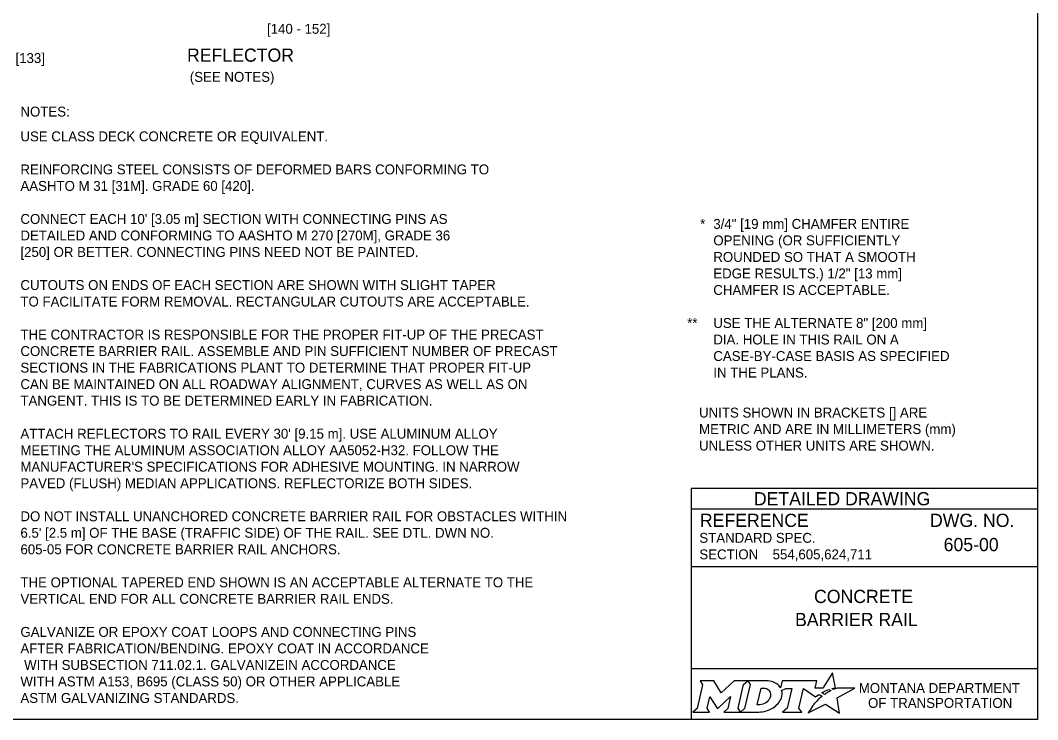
# Model space of a CAD drawing. Extents: x 49991.4 to 50021, y 49987.6 to 50011.4.
# Drawn here: x 50010.59 to 50016.75, y 49987.8 to 49992.03 of the extents above; entities that cross this region are included whole.
import ezdxf

# ---------------------------------------------------------------- set-up
doc = ezdxf.new("R2010")
doc.units = 0
for name, color, linetype in [('Default', 7, 'Continuous'), ('Level 1', 7, 'Continuous'), ('Level 2', 7, 'Continuous'), ('Level 3', 7, 'Continuous'), ('Level 5', 7, 'Continuous')]:
    doc.layers.add(name, color=color, linetype=linetype)

msp = doc.modelspace()

# ---------------------------------------------------------------- linework, layer by layer
at = {"layer": 'Default'}
for points in [[(50014.7056, 49988.0338), (50014.7197, 49988.0104), (50014.6862, 49987.8671), (50014.6605, 49987.8446), (50014.7621, 49987.8446), (50014.7486, 49987.8674), (50014.7648, 49987.9375), (50014.8085, 49987.8685), (50014.8138, 49987.8685), (50014.8889, 49987.938), (50014.8725, 49987.8669), (50014.8478, 49987.8449), (50014.9494, 49987.8449), (50014.9356, 49987.8682), (50014.9688, 49988.0106)], [(50014.9688, 49988.0106), (50014.9941, 49988.0338), (50014.9117, 49988.0338), (50014.8321, 49987.9608), (50014.7876, 49988.0335), (50014.7056, 49988.0338)], [(50015.1077, 49988.0338), (50014.9941, 49988.0338), (50015.0088, 49988.0109), (50014.9749, 49987.8671), (50014.9494, 49987.8449), (50015.06, 49987.8449)], [(50015.5126, 49987.9811), (50015.5023, 49987.9867), (50015.5139, 49987.9895), (50015.5255, 49987.9915), (50015.5081, 49988.0816), (50015.4486, 49987.9903), (50015.4013, 49987.9896), (50015.4116, 49988.0337), (50015.2024, 49988.0338), (50015.1923, 49987.9913), (50015.1865, 49987.9996)], [(50015.1317, 49987.9471), (50015.1305, 49987.939), (50015.1273, 49987.9297), (50015.1231, 49987.9215), (50015.1175, 49987.914), (50015.111, 49987.9071), (50015.1031, 49987.9008), (50015.0948, 49987.8961), (50015.0857, 49987.8922), (50015.0766, 49987.8899), (50015.0674, 49987.889), (50015.0515, 49987.889), (50015.0751, 49987.989), (50015.0911, 49987.989), (50015.0987, 49987.9884), (50015.1063, 49987.9865), (50015.1129, 49987.9835), (50015.119, 49987.9793), (50015.1238, 49987.9743), (50015.1275, 49987.9683), (50015.1302, 49987.9621), (50015.1318, 49987.9547), (50015.1318, 49987.9517), (50015.1317, 49987.9471)], [(50015.1991, 49987.9747), (50015.2237, 49987.9878), (50015.2606, 49987.9878), (50015.232, 49987.8673), (50015.2045, 49987.8446), (50015.3207, 49987.8446), (50015.3037, 49987.8675), (50015.3319, 49987.9877), (50015.4032, 49987.936), (50015.4243, 49987.9511), (50015.444, 49987.9402)], [(50015.3882, 49987.8843), (50015.3729, 49987.8599), (50015.3682, 49987.8524), (50015.3624, 49987.8438), (50015.3601, 49987.8395), (50015.4654, 49987.8926), (50015.5493, 49987.8375), (50015.5362, 49987.9302), (50015.6431, 49987.9886), (50015.5938, 49987.9894), (50015.5637, 49987.9898), (50015.5429, 49987.9901), (50015.5361, 49987.9886), (50015.5312, 49987.9874), (50015.5228, 49987.9851), (50015.5126, 49987.9811)], [(50015.4622, 49987.9535), (50015.4598, 49987.9518), (50015.4415, 49987.9614), (50015.4518, 49987.9671), (50015.4559, 49987.9693), (50015.4645, 49987.9733), (50015.4702, 49987.9759), (50015.4781, 49987.9789), (50015.4854, 49987.9816), (50015.4972, 49987.9742), (50015.4932, 49987.9721), (50015.4886, 49987.9696), (50015.4844, 49987.9674), (50015.4794, 49987.9645), (50015.4775, 49987.9634), (50015.4748, 49987.9618), (50015.4723, 49987.9604), (50015.47, 49987.9588), (50015.4674, 49987.957), (50015.4647, 49987.9552), (50015.4622, 49987.9535)], [(50015.1057, 49987.8522), (50015.1141, 49987.8548), (50015.1271, 49987.8602), (50015.1475, 49987.8712)], [(50015.4021, 49987.9004), (50015.4021, 49987.9004)]]:
    msp.add_lwpolyline(points, dxfattribs=at)
for centre, radius, start, end in [((50015.1308, 49987.9554), 0.0709, 339.53292, 15.85821), ((50015.0868, 49987.9727), 0.1183, 300.91025, 339.13831)]:
    msp.add_arc(centre, radius, start, end, dxfattribs=at)
for centre, major_axis, ratio, start_param, end_param in [((50015.1056, 49987.9864), (0.0834, -0.0037), 0.568097, 0.61298, 1.570796), ((50015.1612, 49987.9937), (0.0361, -0.0295), 0.469099, 1.225588, 1.570796), ((50015.4119, 49987.9106), (-0.0098, -0.0102), 0.016458, 3.141593, 6.279097), ((50015.4329, 49987.9305), (-0.0112, -0.0097), 0.021651, 3.157348, 6.283185), ((50015.0603, 49987.9932), (0, 0.1484), 0.987302, 3.139398, 3.456847), ((50015.3952, 49987.8923), (-0.00694, -0.00806), 0.008222, 0, 3.137361)]:
    msp.add_ellipse(centre, major_axis=major_axis, ratio=ratio, start_param=start_param, end_param=end_param, dxfattribs=at)
at = {"layer": 'Level 1'}
msp.add_lwpolyline([(49999.3835, 49998.9992), (50016.7501, 49998.9992), (50016.7501, 49987.7988), (49999.3835, 49987.7988)], close=True, dxfattribs=at)
at = {"layer": 'Level 5'}
for p, q in [((50016.7501, 49989.1988), (50014.6501, 49989.1988)), ((50014.6501, 49989.1988), (50014.6501, 49987.7988)), ((50016.7501, 49989.0738), (50014.6501, 49989.0738)), ((50016.3862, 49988.8587), (50016.3862, 49988.8587)), ((50015.1444, 49988.7993), (50015.1444, 49988.7993)), ((50016.7501, 49988.7238), (50014.6501, 49988.7238)), ((50015.7001, 49988.4747), (50015.7001, 49988.4747)), ((50016.7501, 49988.1057), (50014.6501, 49988.1057))]:
    msp.add_line(p, q, dxfattribs=at)

# ---------------------------------------------------------------- texts
at = {"layer": 'Default'}
for s, p in [('MONTANA DEPARTMENT', (50015.6663, 49987.96)), ('OF TRANSPORTATION', (50015.7225, 49987.87))]:
    msp.add_text(s, height=0.06, dxfattribs=at).set_placement(p)
at = {"layer": 'Level 2'}
for s, height, p in [('[140 - 152]', 0.06, (50012.0809, 49991.9511)), ('REFLECTOR', 0.08, (50011.5965, 49991.7817)), ('5 1/4" [133]', 0.06, (50010.3279, 49991.774)), ('(SEE NOTES)', 0.06, (50011.6132, 49991.6601)), ('NOTES:', 0.06, (50010.587, 49991.4499)), ('*', 0.06, (50014.7054, 49990.77)), ('3/4" [19 mm] CHAMFER ENTIRE ', 0.06, (50014.7851, 49990.77)), ('OPENING (OR SUFFICIENTLY ', 0.06, (50014.7851, 49990.67)), ('ROUNDED SO THAT A SMOOTH ', 0.06, (50014.7851, 49990.57)), ('EDGE RESULTS.) 1/2" [13 mm] ', 0.06, (50014.7851, 49990.47)), ('CHAMFER IS ACCEPTABLE.', 0.06, (50014.7851, 49990.37)), ('**', 0.06, (50014.6266, 49990.17)), ('USE THE ALTERNATE 8" [200 mm] ', 0.06, (50014.7851, 49990.17)), ('DIA. HOLE IN THIS RAIL ON A ', 0.06, (50014.7851, 49990.07)), ('CASE-BY-CASE BASIS AS SPECIFIED', 0.06, (50014.7851, 49989.97)), ('IN THE PLANS.', 0.06, (50014.7851, 49989.87)), ('UNITS SHOWN IN BRACKETS [] ARE ', 0.06, (50014.6987, 49989.6278)), ('METRIC AND ARE IN MILLIMETERS (mm) ', 0.06, (50014.6987, 49989.5278)), ('UNLESS OTHER UNITS ARE SHOWN.', 0.06, (50014.6987, 49989.4278)), ('605-00', 0.08, (50016.1806, 49988.8187)), ('554,605,624,711', 0.059999, (50015.1444, 49988.7693)), ('CONCRETE', 0.08, (50015.3953, 49988.5047)), ('BARRIER RAIL', 0.079998, (50015.2803, 49988.3647))]:
    msp.add_text(s, height=height, dxfattribs=at).set_placement(p)
at = {"layer": 'Level 3'}
for s, p in [('USE CLASS DECK CONCRETE OR EQUIVALENT.', (50010.587, 49991.2999)), ('REINFORCING STEEL CONSISTS OF DEFORMED BARS CONFORMING TO ', (50010.587, 49991.0999)), ('AASHTO M 31 [31M]. GRADE 60 [420].', (50010.587, 49990.9999)), ("CONNECT EACH 10' [3.05 m] SECTION WITH CONNECTING PINS AS", (50010.587, 49990.7999)), ('DETAILED AND CONFORMING TO AASHTO M 270 [270M], GRADE 36 ', (50010.587, 49990.6999)), ('[250] OR BETTER. CONNECTING PINS NEED NOT BE PAINTED.', (50010.587, 49990.5999)), ('CUTOUTS ON ENDS OF EACH SECTION ARE SHOWN WITH SLIGHT TAPER', (50010.587, 49990.3999)), ('TO FACILITATE FORM REMOVAL. RECTANGULAR CUTOUTS ARE ACCEPTABLE.', (50010.587, 49990.2999)), ('THE CONTRACTOR IS RESPONSIBLE FOR THE PROPER FIT-UP OF THE PRECAST', (50010.587, 49990.0999)), ('CONCRETE BARRIER RAIL. ASSEMBLE AND PIN SUFFICIENT NUMBER OF PRECAST ', (50010.587, 49989.9999)), ('SECTIONS IN THE FABRICATIONS PLANT TO DETERMINE THAT PROPER FIT-UP', (50010.587, 49989.8999)), ('CAN BE MAINTAINED ON ALL ROADWAY ALIGNMENT, CURVES AS WELL AS ON ', (50010.587, 49989.7999)), ('TANGENT. THIS IS TO BE DETERMINED EARLY IN FABRICATION.', (50010.587, 49989.6999)), ("ATTACH REFLECTORS TO RAIL EVERY 30' [9.15 m]. USE ALUMINUM ALLOY", (50010.587, 49989.4999)), ('MEETING THE ALUMINUM ASSOCIATION ALLOY AA5052-H32. FOLLOW THE ', (50010.587, 49989.3999)), ("MANUFACTURER'S SPECIFICATIONS FOR ADHESIVE MOUNTING. IN NARROW", (50010.587, 49989.2999)), ('PAVED (FLUSH) MEDIAN APPLICATIONS. REFLECTORIZE BOTH SIDES.', (50010.587, 49989.1999)), ('DO NOT INSTALL UNANCHORED CONCRETE BARRIER RAIL FOR OBSTACLES WITHIN', (50010.587, 49988.9999)), ("6.5' [2.5 m] OF THE BASE (TRAFFIC SIDE) OF THE RAIL. SEE DTL. DWN NO.", (50010.587, 49988.8999)), ('605-05 FOR CONCRETE BARRIER RAIL ANCHORS.', (50010.587, 49988.7999)), ('THE OPTIONAL TAPERED END SHOWN IS AN ACCEPTABLE ALTERNATE TO THE', (50010.587, 49988.5999)), ('VERTICAL END FOR ALL CONCRETE BARRIER RAIL ENDS. ', (50010.587, 49988.4999)), ('GALVANIZE OR EPOXY COAT LOOPS AND CONNECTING PINS ', (50010.587, 49988.2999)), ('AFTER FABRICATION/BENDING. EPOXY COAT IN ACCORDANCE', (50010.587, 49988.1999)), (' WITH SUBSECTION 711.02.1. GALVANIZEIN ACCORDANCE ', (50010.587, 49988.0999)), ('WITH ASTM A153, B695 (CLASS 50) OR OTHER APPLICABLE', (50010.587, 49987.9999)), ('ASTM GALVANIZING STANDARDS.', (50010.587, 49987.8999))]:
    msp.add_text(s, height=0.06, dxfattribs=at).set_placement(p)
at = {"layer": 'Level 5'}
for s, height, p in [('DETAILED DRAWING', 0.0799, (50015.0311, 49989.0963)), ('REFERENCE', 0.08, (50014.7037, 49988.9654)), ('DWG. NO.', 0.08, (50016.0979, 49988.9654)), ('STANDARD SPEC.', 0.06, (50014.7004, 49988.8694)), ('SECTION', 0.06, (50014.7004, 49988.7694))]:
    msp.add_text(s, height=height, dxfattribs=at).set_placement(p)

doc.saveas('drawing.dxf')
